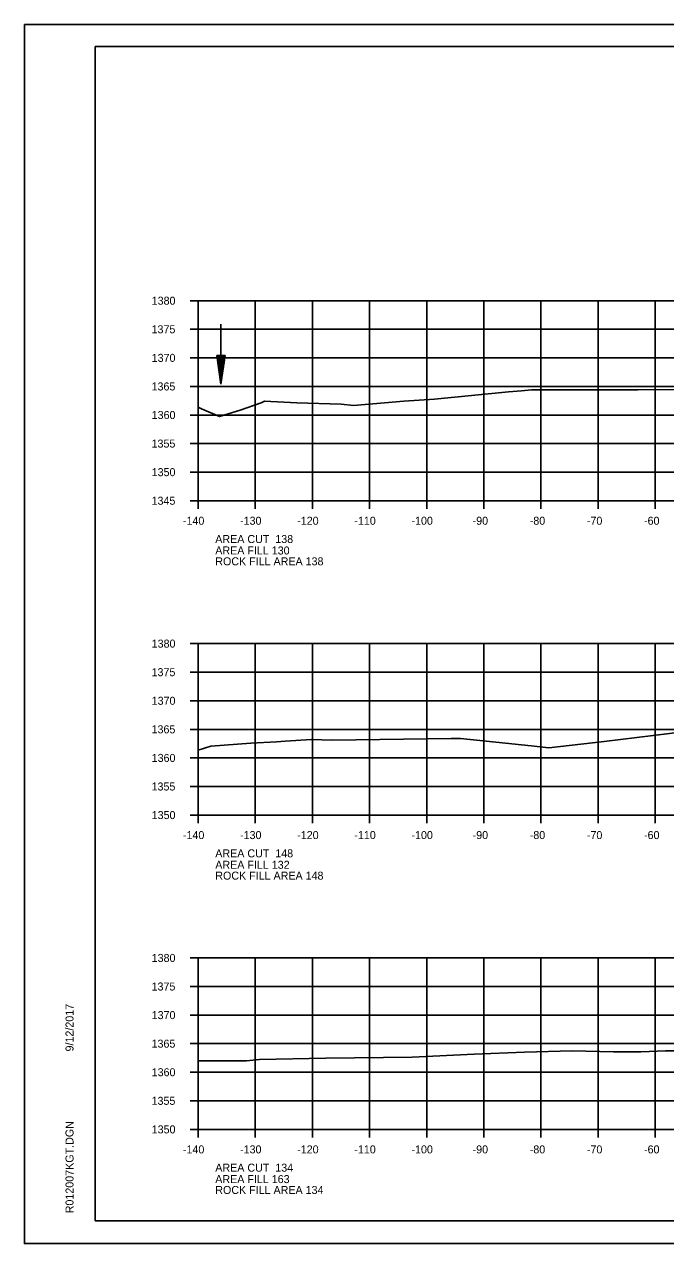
# Model space of a CAD drawing. Extents: x 1374311 to 1383814, y 384102 to 406278.
# Drawn here: x 1381458.2 to 1381570.5, y 391364.8 to 391578.1 of the extents above; entities that cross this region are included whole.
import ezdxf

# ---------------------------------------------------------------- set-up
doc = ezdxf.new("R2010")
doc.units = 0
for name, color, linetype in [('R_Axis', 7, 'Continuous'), ('R_Axis Annot', 7, 'Continuous'), ('R_Border', 7, 'Continuous'), ('R_Draft', 7, 'Continuous'), ('R_Exist Surface', 7, 'Continuous'), ('R_Grid', 7, 'Continuous'), ('R_No Plot', 7, 'Continuous'), ('R_Water', 7, 'Continuous')]:
    doc.layers.add(name, color=color, linetype=linetype)

msp = doc.modelspace()

# ---------------------------------------------------------------- linework, layer by layer
at = {"layer": 'R_Axis'}
for p, q in [((1381487.26, 391529.74), (1381488.66, 391529.74)), ((1381488.66, 391494.74), (1381488.66, 391529.74)), ((1381487.26, 391524.74), (1381488.66, 391524.74)), ((1381487.26, 391519.74), (1381488.66, 391519.74)), ((1381487.26, 391514.74), (1381488.66, 391514.74)), ((1381487.26, 391509.74), (1381488.66, 391509.74)), ((1381487.26, 391504.74), (1381488.66, 391504.74)), ((1381487.26, 391499.74), (1381488.66, 391499.74)), ((1381487.26, 391494.74), (1381488.66, 391494.74)), ((1381488.66, 391494.74), (1381768.66, 391494.74)), ((1381488.66, 391493.34), (1381488.66, 391494.74)), ((1381498.66, 391493.34), (1381498.66, 391494.74)), ((1381508.66, 391493.34), (1381508.66, 391494.74)), ((1381518.66, 391493.34), (1381518.66, 391494.74)), ((1381528.66, 391493.34), (1381528.66, 391494.74)), ((1381538.66, 391493.34), (1381538.66, 391494.74)), ((1381548.66, 391493.34), (1381548.66, 391494.74)), ((1381558.66, 391493.34), (1381558.66, 391494.74)), ((1381568.66, 391493.34), (1381568.66, 391494.74)), ((1381487.26, 391469.74), (1381488.66, 391469.74)), ((1381488.66, 391439.74), (1381488.66, 391469.74)), ((1381487.26, 391464.74), (1381488.66, 391464.74)), ((1381487.26, 391459.74), (1381488.66, 391459.74)), ((1381487.26, 391454.74), (1381488.66, 391454.74)), ((1381487.26, 391449.74), (1381488.66, 391449.74)), ((1381487.26, 391444.74), (1381488.66, 391444.74)), ((1381487.26, 391439.74), (1381488.66, 391439.74)), ((1381488.66, 391439.74), (1381768.66, 391439.74)), ((1381488.66, 391438.34), (1381488.66, 391439.74)), ((1381498.66, 391438.34), (1381498.66, 391439.74)), ((1381508.66, 391438.34), (1381508.66, 391439.74)), ((1381518.66, 391438.34), (1381518.66, 391439.74)), ((1381528.66, 391438.34), (1381528.66, 391439.74)), ((1381538.66, 391438.34), (1381538.66, 391439.74)), ((1381548.66, 391438.34), (1381548.66, 391439.74)), ((1381558.66, 391438.34), (1381558.66, 391439.74)), ((1381568.66, 391438.34), (1381568.66, 391439.74)), ((1381487.26, 391414.74), (1381488.66, 391414.74)), ((1381488.66, 391384.74), (1381488.66, 391414.74)), ((1381487.26, 391409.74), (1381488.66, 391409.74)), ((1381487.26, 391404.74), (1381488.66, 391404.74)), ((1381487.26, 391399.74), (1381488.66, 391399.74)), ((1381487.26, 391394.74), (1381488.66, 391394.74)), ((1381487.26, 391389.74), (1381488.66, 391389.74)), ((1381487.26, 391384.74), (1381488.66, 391384.74)), ((1381488.66, 391384.74), (1381768.66, 391384.74)), ((1381488.66, 391383.34), (1381488.66, 391384.74)), ((1381498.66, 391383.34), (1381498.66, 391384.74)), ((1381508.66, 391383.34), (1381508.66, 391384.74)), ((1381518.66, 391383.34), (1381518.66, 391384.74)), ((1381528.66, 391383.34), (1381528.66, 391384.74)), ((1381538.66, 391383.34), (1381538.66, 391384.74)), ((1381548.66, 391383.34), (1381548.66, 391384.74)), ((1381558.66, 391383.34), (1381558.66, 391384.74)), ((1381568.66, 391383.34), (1381568.66, 391384.74))]:
    msp.add_line(p, q, dxfattribs=at)
at = {"layer": 'R_Border'}
for p, q in [((1381470.66, 391574.2), (1381786.84, 391574.2)), ((1381470.66, 391368.74), (1381470.66, 391574.2)), ((1381470.66, 391368.74), (1381470.66, 391368.74)), ((1381786.84, 391368.74), (1381470.66, 391368.74))]:
    msp.add_line(p, q, dxfattribs=at)
at = {"layer": 'R_Draft'}
for p, q in [((1381491.91, 391520.15), (1381492.66, 391515.15)), ((1381493.41, 391520.15), (1381491.91, 391520.15)), ((1381492.03, 391520.15), (1381492.66, 391515.99)), ((1381492.16, 391520.15), (1381492.66, 391516.85)), ((1381492.28, 391520.15), (1381492.66, 391517.68)), ((1381492.41, 391520.15), (1381492.66, 391518.53)), ((1381492.54, 391520.15), (1381492.66, 391519.36)), ((1381493.41, 391520.15), (1381492.66, 391515.15)), ((1381492.9, 391520.15), (1381492.66, 391518.53)), ((1381493.15, 391520.15), (1381492.66, 391516.85)), ((1381493.28, 391520.15), (1381492.66, 391515.99)), ((1381493.03, 391520.15), (1381492.66, 391517.68)), ((1381492.77, 391520.15), (1381492.66, 391519.36))]:
    msp.add_line(p, q, dxfattribs=at)
at = {"layer": 'R_Exist Surface'}
for points in [[(1381488.66, 391511.11), (1381489.25, 391510.85), (1381492.42, 391509.46), (1381496.02, 391510.58), (1381499.69, 391511.9), (1381500.27, 391512.14), (1381505.93, 391511.9), (1381513.7, 391511.62), (1381515.86, 391511.42), (1381524.68, 391512.15), (1381530.05, 391512.52), (1381542.96, 391513.77), (1381545.24, 391513.97), (1381546.98, 391514.17), (1381559.88, 391514.13), (1381565.59, 391514.16), (1381578.71, 391514.22)], [(1381488.66, 391451.09), (1381490.87, 391451.78), (1381497.9, 391452.33), (1381502.39, 391452.56), (1381503.91, 391452.66), (1381508.5, 391452.94), (1381512.11, 391452.87), (1381532.95, 391453.12), (1381533.9, 391453.13), (1381534.55, 391453.14), (1381546.93, 391451.88), (1381550.04, 391451.52), (1381559.74, 391452.62), (1381573.99, 391454.36)], [(1381488.66, 391396.73), (1381490.28, 391396.73), (1381497.11, 391396.76), (1381499.4, 391396.96), (1381511.03, 391397.21), (1381526.14, 391397.38), (1381537, 391397.93), (1381545.76, 391398.26), (1381554.11, 391398.47), (1381561.35, 391398.33), (1381566.17, 391398.34), (1381570.44, 391398.47), (1381574.42, 391398.46)]]:
    msp.add_lwpolyline(points, dxfattribs=at)
at = {"layer": 'R_Grid'}
for p, q in [((1381488.66, 391529.74), (1381768.66, 391529.74)), ((1381488.66, 391494.74), (1381488.66, 391529.74)), ((1381498.66, 391494.74), (1381498.66, 391529.74)), ((1381508.66, 391494.74), (1381508.66, 391529.74)), ((1381518.66, 391494.74), (1381518.66, 391529.74)), ((1381528.66, 391494.74), (1381528.66, 391529.74)), ((1381538.66, 391494.74), (1381538.66, 391529.74)), ((1381548.66, 391494.74), (1381548.66, 391529.74)), ((1381558.66, 391494.74), (1381558.66, 391529.74)), ((1381568.66, 391494.74), (1381568.66, 391529.74)), ((1381488.66, 391524.74), (1381768.66, 391524.74)), ((1381488.66, 391519.74), (1381768.66, 391519.74)), ((1381488.66, 391514.74), (1381768.66, 391514.74)), ((1381488.66, 391509.74), (1381768.66, 391509.74)), ((1381488.66, 391504.74), (1381768.66, 391504.74)), ((1381488.66, 391499.74), (1381768.66, 391499.74)), ((1381488.66, 391494.74), (1381768.66, 391494.74)), ((1381488.66, 391469.74), (1381768.66, 391469.74)), ((1381488.66, 391439.74), (1381488.66, 391469.74)), ((1381498.66, 391439.74), (1381498.66, 391469.74)), ((1381508.66, 391439.74), (1381508.66, 391469.74)), ((1381518.66, 391439.74), (1381518.66, 391469.74)), ((1381528.66, 391439.74), (1381528.66, 391469.74)), ((1381538.66, 391439.74), (1381538.66, 391469.74)), ((1381548.66, 391439.74), (1381548.66, 391469.74)), ((1381558.66, 391439.74), (1381558.66, 391469.74)), ((1381568.66, 391439.74), (1381568.66, 391469.74)), ((1381488.66, 391464.74), (1381768.66, 391464.74)), ((1381488.66, 391459.74), (1381768.66, 391459.74)), ((1381488.66, 391454.74), (1381768.66, 391454.74)), ((1381488.66, 391449.74), (1381768.66, 391449.74)), ((1381488.66, 391444.74), (1381768.66, 391444.74)), ((1381488.66, 391439.74), (1381768.66, 391439.74)), ((1381488.66, 391414.74), (1381768.66, 391414.74)), ((1381488.66, 391384.74), (1381488.66, 391414.74)), ((1381498.66, 391384.74), (1381498.66, 391414.74)), ((1381508.66, 391384.74), (1381508.66, 391414.74)), ((1381518.66, 391384.74), (1381518.66, 391414.74)), ((1381528.66, 391384.74), (1381528.66, 391414.74)), ((1381538.66, 391384.74), (1381538.66, 391414.74)), ((1381548.66, 391384.74), (1381548.66, 391414.74)), ((1381558.66, 391384.74), (1381558.66, 391414.74)), ((1381568.66, 391384.74), (1381568.66, 391414.74)), ((1381488.66, 391409.74), (1381768.66, 391409.74)), ((1381488.66, 391404.74), (1381768.66, 391404.74)), ((1381488.66, 391399.74), (1381768.66, 391399.74)), ((1381488.66, 391394.74), (1381768.66, 391394.74)), ((1381488.66, 391389.74), (1381768.66, 391389.74)), ((1381488.66, 391384.74), (1381768.66, 391384.74))]:
    msp.add_line(p, q, dxfattribs=at)
at = {"layer": 'R_No Plot'}
for p, q in [((1381458.26, 391578.09), (1381791.59, 391578.09)), ((1381458.26, 391364.76), (1381791.59, 391364.76))]:
    msp.add_line(p, q, dxfattribs=at)
for points in [[(1381458.25, 391578.09), (1381791.59, 391578.09), (1381791.59, 391364.75), (1381458.25, 391364.75)], [(1381704.58, 391574.2), (1381704.58, 391564.32), (1381740.31, 391564.32), (1381740.31, 391561.4), (1381763.51, 391561.4), (1381763.51, 391538.18), (1381786.84, 391538.18), (1381786.84, 391368.74), (1381470.66, 391368.74), (1381470.66, 391574.2)]]:
    msp.add_lwpolyline(points, close=True, dxfattribs=at)
at = {"layer": 'R_Water'}
msp.add_line((1381492.66, 391525.66), (1381492.66, 391515.15), dxfattribs=at)

# ---------------------------------------------------------------- texts
at = {"layer": 'R_Axis Annot'}
for s, p in [('1380', (1381480.53, 391529.04)), ('1375', (1381480.51, 391524.04)), ('1370', (1381480.53, 391519.04)), ('1365', (1381480.51, 391514.04)), ('1360', (1381480.53, 391509.04)), ('1355', (1381480.51, 391504.04)), ('1350', (1381480.53, 391499.04)), ('1345', (1381480.51, 391494.04)), ('-140', (1381486, 391490.54)), ('-130', (1381496, 391490.54)), ('-120', (1381506, 391490.54)), ('-110', (1381516, 391490.54)), ('-100', (1381526, 391490.54)), ('-90', (1381536.7, 391490.54)), ('-80', (1381546.7, 391490.54)), ('-70', (1381556.7, 391490.54)), ('-60', (1381566.7, 391490.54)), ('AREA CUT  138', (1381491.66, 391487.34)), ('AREA FILL 130', (1381491.66, 391485.34)), ('ROCK FILL AREA 138', (1381491.66, 391483.44)), ('1380', (1381480.53, 391469.04)), ('1375', (1381480.51, 391464.04)), ('1370', (1381480.53, 391459.04)), ('1365', (1381480.51, 391454.04)), ('1360', (1381480.53, 391449.04)), ('1355', (1381480.51, 391444.04)), ('1350', (1381480.53, 391439.04)), ('-140', (1381486, 391435.54)), ('-130', (1381496, 391435.54)), ('-120', (1381506, 391435.54)), ('-110', (1381516, 391435.54)), ('-100', (1381526, 391435.54)), ('-90', (1381536.7, 391435.54)), ('-80', (1381546.7, 391435.54)), ('-70', (1381556.7, 391435.54)), ('-60', (1381566.7, 391435.54)), ('AREA CUT  148', (1381491.66, 391432.34)), ('AREA FILL 132', (1381491.66, 391430.34)), ('ROCK FILL AREA 148', (1381491.66, 391428.44)), ('1380', (1381480.53, 391414.04)), ('1375', (1381480.51, 391409.04)), ('1370', (1381480.53, 391404.04)), ('1365', (1381480.51, 391399.04)), ('1360', (1381480.53, 391394.04)), ('1355', (1381480.51, 391389.04)), ('1350', (1381480.53, 391384.04)), ('-140', (1381486, 391380.54)), ('-130', (1381496, 391380.54)), ('-120', (1381506, 391380.54)), ('-110', (1381516, 391380.54)), ('-100', (1381526, 391380.54)), ('-90', (1381536.7, 391380.54)), ('-80', (1381546.7, 391380.54)), ('-70', (1381556.7, 391380.54)), ('-60', (1381566.7, 391380.54)), ('AREA CUT  134', (1381491.66, 391377.34)), ('AREA FILL 163', (1381491.66, 391375.34)), ('ROCK FILL AREA 134', (1381491.66, 391373.44))]:
    msp.add_text(s, height=1.4, dxfattribs=at).set_placement(p)
at = {"layer": 'R_Border'}
for s, p in [('9/12/2017', (1381466.85, 391398.38)), ('R012007KGT.DGN', (1381466.85, 391370.06))]:
    msp.add_text(s, height=1.4, rotation=90, dxfattribs=at).set_placement(p)

doc.saveas('drawing.dxf')
